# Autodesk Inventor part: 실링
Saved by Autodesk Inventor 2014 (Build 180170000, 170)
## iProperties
Created: 2026-03
Part Number: 실링
Material: 일반
Document SubType Name: Modeling
Designer: dg
Density: 1 g/cm^3
Appearance: 기본값
Author: dg
Author: jhkim
Creation Date: 2025-06-27
Sending System: Autodesk Inventor 2026
Preprocessor: ST-DEVELOPER v20.1
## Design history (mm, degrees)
node "실링1"
node "솔리드1"
node "기준1"
